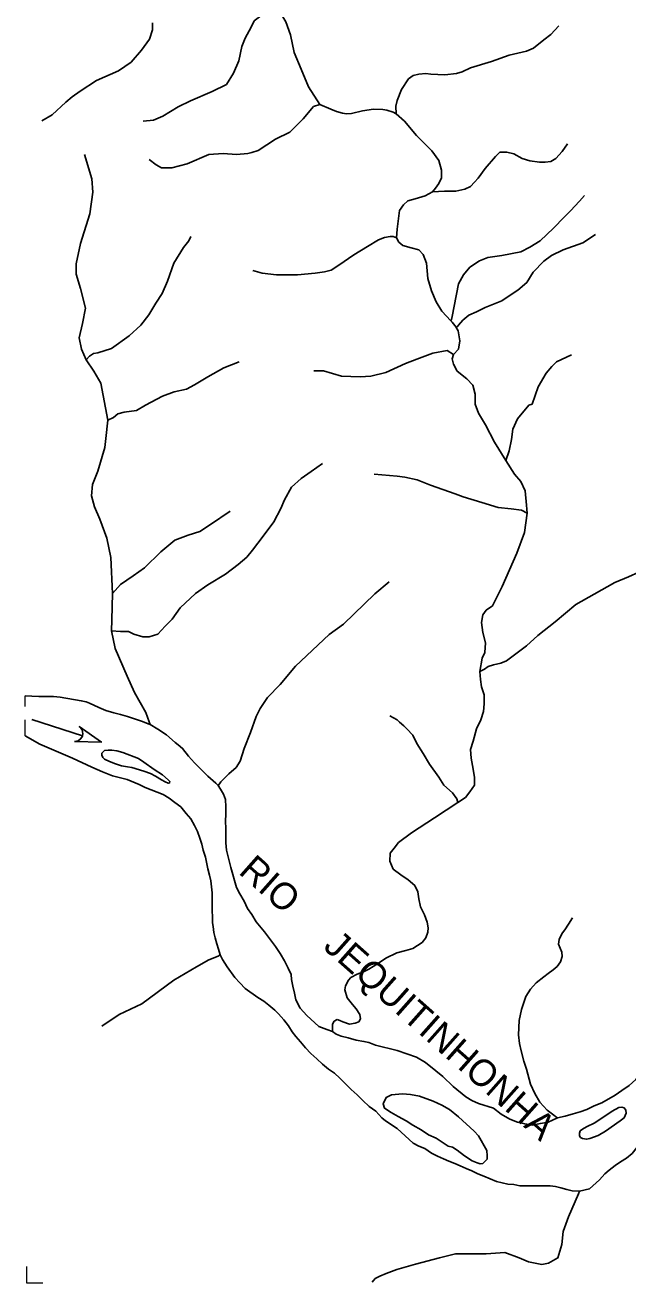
# Model space of a CAD drawing. Extents: x 436.3 to 500.4, y 8231 to 8286.4.
# Drawn here: x 446.49 to 451, y 8230.98 to 8240.38 of the extents above; entities that cross this region are included whole.
import ezdxf
from ezdxf.enums import TextEntityAlignment as Align

# ---------------------------------------------------------------- set-up
doc = ezdxf.new("R2010")
doc.units = 0
doc.header["$LTSCALE"] = 0.08
doc.linetypes.add('LONG_DASHED', pattern=[7.5, 6, -1.5])
doc.linetypes.add('SHORT_DASHED', pattern=[2.7, 1.5, -1.2])
for name, color, linetype, lineweight in [('10', 7, 'Continuous', 25), ('2', 7, 'Continuous', 25), ('62', 7, 'SHORT_DASHED', 13), ('63', 7, 'Continuous', 13), ('7', 7, 'Continuous', 25), ('9', 7, 'LONG_DASHED', 25)]:
    doc.layers.add(name, color=color, linetype=linetype, lineweight=lineweight)
doc.layers.add('61', color=7, linetype='Continuous')

msp = doc.modelspace()

# ---------------------------------------------------------------- linework, layer by layer
at = {"layer": '10'}
msp.add_line((446.5406, 8235.1881), (446.919, 8235.0658), dxfattribs=at)
msp.add_lwpolyline([(446.859, 8235.0241), (446.8761, 8235.0264), (446.8873, 8235.0299), (446.9031, 8235.0408), (446.9166, 8235.0591), (446.919, 8235.0658), (446.9219, 8235.0823), (446.9204, 8235.0973), (446.9164, 8235.1116), (446.908, 8235.1238), (446.8951, 8235.1357), (447.0619, 8235.0197)], close=True, dxfattribs=at)
at = {"layer": '2'}
for points in [[(447.4257, 8235.1524), (447.4106, 8235.1558), (447.3801, 8235.1688), (447.3615, 8235.1755), (447.2577, 8235.2116), (447.2035, 8235.2251), (447.1539, 8235.2387), (447.0952, 8235.2567), (447.0411, 8235.2793), (446.9734, 8235.3108), (446.9463, 8235.3198), (446.9102, 8235.3289), (446.7522, 8235.3561), (446.7026, 8235.3607), (446.5943, 8235.3608), (446.5402, 8235.363), (446.4909, 8235.3646)], [(447.9336, 8234.6948), (447.9163, 8234.712), (447.8577, 8234.766), (447.7584, 8234.8649), (447.7133, 8234.9144), (447.6682, 8234.9729), (447.6367, 8234.9999), (447.6141, 8235.0179), (447.5484, 8235.0732), (447.4833, 8235.1169), (447.4257, 8235.1524)], [(446.4916, 8235.0661), (446.6012, 8235.0056), (446.8464, 8234.8998), (446.9905, 8234.8321), (447.0699, 8234.799), (447.1445, 8234.767), (447.2529, 8234.7399), (447.3431, 8234.7038), (447.3882, 8234.6813), (447.5236, 8234.6272), (447.5687, 8234.6001), (447.6094, 8234.5686), (447.6545, 8234.5371), (447.6951, 8234.4876), (447.7312, 8234.4472), (447.7582, 8234.3977), (447.7808, 8234.3527), (447.7988, 8234.3033), (447.8123, 8234.2583), (447.8213, 8234.2134), (447.8393, 8234.1595), (447.8573, 8234.0741), (447.8708, 8234.0246), (447.8799, 8233.9842), (447.8888, 8233.8943), (447.8887, 8233.7595), (447.8932, 8233.7146), (447.8932, 8233.6697), (447.8977, 8233.6427), (447.9022, 8233.5978), (447.9112, 8233.5573), (447.9247, 8233.5124), (447.9382, 8233.4719), (447.9495, 8233.4305)], [(448.5157, 8233.0936), (448.5067, 8233.1431), (448.4932, 8233.197), (448.4842, 8233.2464), (448.4797, 8233.2824), (448.4572, 8233.3318), (448.4302, 8233.3858), (448.3986, 8233.4397), (448.3625, 8233.4937), (448.2814, 8233.6017), (448.2182, 8233.6781), (448.1866, 8233.7321), (448.1551, 8233.7771), (448.128, 8233.831), (448.0965, 8233.885), (448.0727, 8233.9344), (448.0297, 8234.0827), (447.9973, 8234.2131), (447.9928, 8234.2671), (447.9929, 8234.3749), (447.9884, 8234.4288), (447.9929, 8234.4827), (447.993, 8234.5366), (447.9885, 8234.5906), (447.975, 8234.631), (447.9509, 8234.6684), (447.9336, 8234.6948)], [(447.9495, 8233.4305), (447.9678, 8233.3964), (448.0013, 8233.3415), (448.06, 8233.2606), (448.0961, 8233.2201), (448.1367, 8233.1796), (448.2314, 8233.112), (448.2765, 8233.085), (448.3126, 8233.0535), (448.3577, 8233.0175), (448.3848, 8232.9905), (448.4254, 8232.9455), (448.4614, 8232.9005), (448.4885, 8232.8556), (448.5155, 8232.8196), (448.5516, 8232.7791), (448.5876, 8232.7341), (448.6282, 8232.6936), (448.6733, 8232.6532), (448.7138, 8232.6127), (448.7589, 8232.5767), (448.804, 8232.5452), (448.8445, 8232.5092), (448.9301, 8232.4238), (448.9752, 8232.3833), (449.0157, 8232.3428), (449.0653, 8232.2979), (449.1148, 8232.2619), (449.1599, 8232.2124), (449.1869, 8232.19), (449.2725, 8232.1315), (449.3941, 8232.0236), (449.4346, 8232.0011), (449.4797, 8231.9831), (449.5292, 8231.9471), (449.5743, 8231.9246), (449.6193, 8231.9066), (449.6599, 8231.8886), (449.7049, 8231.8706), (449.7455, 8231.8526), (449.7905, 8231.8346), (449.8311, 8231.8166), (449.8761, 8231.7941), (449.9212, 8231.7761), (450.0158, 8231.7356), (450.1014, 8231.7176), (450.1465, 8231.713), (450.1915, 8231.704), (450.4169, 8231.7038), (450.4575, 8231.6993), (450.498, 8231.6903), (450.5431, 8231.6768), (450.5836, 8231.6677), (450.6384, 8231.6632)], [(448.7889, 8232.8575), (448.7479, 8232.8729), (448.687, 8232.8957), (448.5969, 8232.9767), (448.5473, 8233.0307), (448.5157, 8233.0936)], [(450.4733, 8232.2117), (450.4359, 8232.1958), (450.404, 8232.1799), (450.3454, 8232.171), (450.2868, 8232.1576), (450.2282, 8232.1666), (450.1742, 8232.1801), (450.1156, 8232.2026), (450.0525, 8232.2386), (449.994, 8232.2836), (449.8813, 8232.3196), (449.8318, 8232.3421), (449.7867, 8232.3691), (449.6922, 8232.4455), (449.6156, 8232.5219), (449.5616, 8232.5624), (449.485, 8232.6254), (449.4174, 8232.6659), (449.2732, 8232.7154), (449.1109, 8232.756), (449.0613, 8232.774), (449.0252, 8232.783), (448.9666, 8232.7921), (448.908, 8232.8101), (448.8539, 8232.8236), (448.8178, 8232.8372), (448.7889, 8232.8575)], [(451.5338, 8232.7256), (451.504, 8232.7208), (451.4903, 8232.7185), (451.4588, 8232.7185), (451.3957, 8232.7095), (451.3371, 8232.6961), (451.3056, 8232.6871), (451.2155, 8232.6422), (451.1614, 8232.6018), (451.1028, 8232.5524), (451.0577, 8232.4985), (451.0081, 8232.4536), (450.954, 8232.4177), (450.9044, 8232.3818), (450.8052, 8232.3234), (450.7466, 8232.301), (450.6925, 8232.2741), (450.6429, 8232.2561), (450.5888, 8232.2427), (450.5302, 8232.2248), (450.4733, 8232.2117)], [(450.9895, 8231.91), (451.0301, 8231.9459), (451.1068, 8232.0402), (451.1925, 8232.1794), (451.2151, 8232.2198), (451.2422, 8232.2603), (451.3053, 8232.3411)], [(450.6384, 8231.6632), (450.7113, 8231.6824), (450.7865, 8231.7484), (450.8271, 8231.7933), (450.8587, 8231.8202), (450.9038, 8231.8561), (450.9444, 8231.8831), (450.9895, 8231.91)]]:
    msp.add_lwpolyline(points, dxfattribs=at)
for points in [[(447.1402, 8234.9602), (447.112, 8234.9602), (447.0848, 8234.9583), (447.065, 8234.9362), (447.065, 8234.9215), (447.0724, 8234.9043), (447.0847, 8234.892), (447.122, 8234.8749), (447.1672, 8234.8568), (447.2123, 8234.8433), (447.2574, 8234.8342), (447.289, 8234.8297), (447.3793, 8234.8026), (447.4289, 8234.7845), (447.465, 8234.7665), (447.5117, 8234.7392), (447.5388, 8234.722), (447.5611, 8234.7122), (447.5709, 8234.7145), (447.5734, 8234.7244), (447.5611, 8234.7391), (447.5192, 8234.7754), (447.456, 8234.8159), (447.3793, 8234.87), (447.3387, 8234.897), (447.2214, 8234.9421), (447.1763, 8234.9556)], [(449.2322, 8232.383), (449.1916, 8232.3651), (449.169, 8232.3157), (449.178, 8232.2843), (449.2276, 8232.2528), (449.2816, 8232.2213), (449.3402, 8232.1898), (449.3898, 8232.1583), (449.4528, 8232.1223), (449.5069, 8232.0863), (449.5655, 8232.0593), (449.6555, 8232.0009), (449.6871, 8231.9919), (449.7231, 8231.9694), (449.7772, 8231.9289), (449.8346, 8231.8914), (449.871, 8231.8749), (449.8942, 8231.8683), (449.914, 8231.8716), (449.9471, 8231.9045), (449.9472, 8231.9276), (449.9439, 8231.9671), (449.881, 8232.077), (449.8495, 8232.113), (449.7325, 8232.2209), (449.6649, 8232.2748), (449.6064, 8232.3063), (449.5433, 8232.3378), (449.4396, 8232.3738), (449.372, 8232.3874), (449.3134, 8232.3919)], [(450.6592, 8232.1279), (450.6427, 8232.1148), (450.636, 8232.0983), (450.636, 8232.0786), (450.6459, 8232.0654), (450.6591, 8232.0588), (450.6889, 8232.0522), (450.7148, 8232.0584), (450.7779, 8232.0808), (450.832, 8232.1123), (450.9404, 8232.1904), (450.9702, 8232.2134), (450.9868, 8232.2463), (450.9835, 8232.2694), (450.9703, 8232.2859), (450.9538, 8232.2925), (450.9306, 8232.2892), (450.8809, 8232.2629), (450.7519, 8232.174), (450.689, 8232.1444)]]:
    msp.add_lwpolyline(points, close=True, dxfattribs=at)
at = {"layer": '62'}
msp.add_line((446.4916, 8235.0661), (446.4909, 8235.3646), dxfattribs=at)
at = {"layer": '63'}
msp.add_lwpolyline([(446.5014, 8231.1023), (446.5014, 8230.9791), (446.6228, 8230.9791)], dxfattribs=at)
at = {"layer": '7'}
msp.add_line((450.6384, 8231.6632), (450.6305, 8231.6443), dxfattribs=at)
msp.add_lwpolyline([(450.6305, 8231.6443), (450.5556, 8231.4724), (450.5157, 8231.3636), (450.5056, 8231.2646), (450.4756, 8231.1658), (450.4059, 8231.1262), (450.3562, 8231.1164), (450.2567, 8231.1363), (450.1872, 8231.1661), (450.0779, 8231.2058), (449.9386, 8231.196), (449.7795, 8231.1962), (449.7099, 8231.1963), (449.5904, 8231.1668), (449.4113, 8231.1175), (449.2719, 8231.0783), (449.1922, 8231.0487), (449.1432, 8231.0287), (449.1101, 8231.011), (449.087, 8230.9851)], dxfattribs=at)
at = {"layer": '9'}
for p, q in [((448.694, 8239.7856), (448.7781, 8239.7493)), ((448.7902, 8232.8734), (448.7889, 8232.8575))]:
    msp.add_line(p, q, dxfattribs=at)
for points in [[(447.3741, 8239.6601), (447.451, 8239.6677), (447.5202, 8239.6982), (447.6356, 8239.7669), (447.7277, 8239.8128), (447.8891, 8239.8815), (447.9969, 8239.935), (448.0506, 8240.0192), (448.0892, 8240.111), (448.1123, 8240.2183), (448.1354, 8240.2794), (448.1816, 8240.3636), (448.2047, 8240.4096), (448.2739, 8240.4631), (448.3046, 8240.4937), (448.3348, 8240.5227)], [(448.3348, 8240.5227), (448.3357, 8240.5218), (448.4029, 8240.4643), (448.4413, 8240.4021), (448.4749, 8240.3064), (448.5036, 8240.1723), (448.5563, 8240.0479), (448.6096, 8239.9156), (448.694, 8239.7856)], [(446.6161, 8239.6634), (446.6928, 8239.7072), (446.7957, 8239.8023), (446.843, 8239.8411), (446.9014, 8239.8849), (447.0249, 8239.9647), (447.1899, 8240.0354), (447.2849, 8240.0999), (447.3618, 8240.1917), (447.4206, 8240.2724), (447.4436, 8240.3426), (447.4437, 8240.3961)], [(450.4815, 8240.3715), (450.424, 8240.309), (450.3716, 8240.2674), (450.2932, 8240.2048), (450.2409, 8240.184), (450.1102, 8240.1528), (449.9795, 8240.1061), (449.8227, 8240.0592), (449.7599, 8240.0279), (449.7181, 8240.0176), (449.6292, 8240.0072), (449.5247, 8240.0124), (449.4881, 8240.0176), (449.4358, 8240.0124), (449.394, 8240.0021), (449.3573, 8239.976), (449.305, 8239.8979), (449.2735, 8239.8146), (449.2631, 8239.7729), (449.2651, 8239.7155)], [(447.418, 8239.3732), (447.4718, 8239.3349), (447.5102, 8239.312), (447.5871, 8239.3119), (447.7024, 8239.3423), (447.8638, 8239.411), (447.9714, 8239.4186), (448.0713, 8239.4109), (448.1558, 8239.4185), (448.1866, 8239.4261), (448.2327, 8239.4413), (448.3634, 8239.5255), (448.471, 8239.579), (448.571, 8239.6784), (448.6479, 8239.7702), (448.694, 8239.7856)], [(448.7781, 8239.7493), (448.8203, 8239.7324), (448.8639, 8239.7207), (448.8943, 8239.7155), (448.9324, 8239.7175), (449.0147, 8239.7376), (449.0956, 8239.7493), (449.1655, 8239.748), (449.1967, 8239.7434), (449.243, 8239.7285), (449.2651, 8239.7155)], [(449.2651, 8239.7155), (449.3295, 8239.66), (449.4169, 8239.5523), (449.5321, 8239.4374), (449.5849, 8239.3656), (449.604, 8239.2939), (449.604, 8239.2364), (449.5847, 8239.1934), (449.5606, 8239.1599), (449.5367, 8239.1312)], [(450.5475, 8239.4899), (450.5066, 8239.4324), (450.4594, 8239.3803), (450.4229, 8239.3595), (450.3811, 8239.3543), (450.3393, 8239.3543), (450.2661, 8239.3649), (450.2087, 8239.3805), (450.146, 8239.417), (450.0937, 8239.4274), (450.0415, 8239.4274), (450.0101, 8239.3961), (449.9315, 8239.3076), (449.8793, 8239.2348), (449.8531, 8239.2036), (449.8217, 8239.1724), (449.7799, 8239.1516), (449.7119, 8239.136), (449.6283, 8239.136), (449.5367, 8239.1312)], [(446.9357, 8239.4119), (446.9894, 8239.2282), (446.9971, 8239.1288), (446.974, 8238.9682), (446.9047, 8238.7465), (446.8738, 8238.5935), (446.8738, 8238.517), (446.9045, 8238.4099), (446.9424, 8238.2617), (446.9193, 8238.147), (446.8961, 8238.04), (446.9114, 8237.9559), (446.9485, 8237.8757)], [(449.5367, 8239.1312), (449.4838, 8239.1026), (449.4069, 8239.0786), (449.3541, 8239.0644), (449.3204, 8239.0357), (449.2916, 8238.9927), (449.2723, 8238.854), (449.2674, 8238.7895)], [(450.6735, 8239.1043), (450.6368, 8239.0627), (450.5688, 8238.9898), (450.5217, 8238.9431), (450.4433, 8238.8598), (450.3439, 8238.7662), (450.2655, 8238.7193), (450.1975, 8238.683), (450.0564, 8238.657), (449.9519, 8238.6415), (449.8892, 8238.6154), (449.816, 8238.5686), (449.7689, 8238.5114), (449.7322, 8238.4438), (449.7008, 8238.2773), (449.6859, 8238.1993), (449.6795, 8238.1775), (449.6761, 8238.1674)], [(447.6021, 8238.5979), (447.6756, 8238.7167), (447.7163, 8238.7666), (447.7302, 8238.7976)], [(448.1941, 8238.5434), (448.2634, 8238.5242), (448.371, 8238.5127), (448.5288, 8238.5126), (448.6596, 8238.524), (448.7289, 8238.5354), (448.7789, 8238.5469), (448.8366, 8238.5851), (448.9482, 8238.6617), (449.0524, 8238.7229), (449.1332, 8238.7727), (449.1794, 8238.7917), (449.2217, 8238.7994), (449.2448, 8238.7994), (449.2674, 8238.7895)], [(449.2674, 8238.7895), (449.2866, 8238.7559), (449.3155, 8238.732), (449.3779, 8238.7129), (449.4355, 8238.6985), (449.4691, 8238.665), (449.4931, 8238.5981), (449.5026, 8238.4834), (449.5313, 8238.3925), (449.5649, 8238.3111), (449.608, 8238.2394), (449.6761, 8238.1674)], [(450.7567, 8238.8128), (450.6626, 8238.7504), (450.5163, 8238.6984), (450.4275, 8238.6566), (450.37, 8238.6151), (450.2915, 8238.5319), (450.2444, 8238.4539), (450.1764, 8238.3966), (450.1032, 8238.3499), (450.0562, 8238.3186), (449.9308, 8238.2667), (449.868, 8238.2354), (449.8105, 8238.2095), (449.7635, 8238.1731), (449.7324, 8238.135), (449.7268, 8238.1282), (449.716, 8238.1179)], [(446.9485, 8237.8757), (446.972, 8237.9034), (447.0026, 8237.9229), (447.0359, 8237.9296), (447.1358, 8237.9625), (447.269, 8238.0551), (447.3557, 8238.1345), (447.4155, 8238.2139), (447.4688, 8238.2999), (447.5155, 8238.3728), (447.5555, 8238.4654), (447.6021, 8238.5979)], [(449.6761, 8238.1674), (449.6848, 8238.1582), (449.7151, 8238.1196), (449.716, 8238.1179)], [(449.716, 8238.1179), (449.7302, 8238.0922), (449.7423, 8238.0176), (449.7327, 8237.9554), (449.6943, 8237.9171)], [(448.6497, 8237.7955), (448.7229, 8237.7955), (448.856, 8237.7557), (448.9958, 8237.749), (449.0755, 8237.7555), (449.1887, 8237.7819), (449.3351, 8237.8482), (449.4216, 8237.8812), (449.5414, 8237.9276), (449.6479, 8237.9474), (449.6943, 8237.9171)], [(446.9485, 8237.8757), (447.004, 8237.7929), (447.0574, 8237.7034), (447.1106, 8237.427)], [(448.0907, 8237.8621), (447.9776, 8237.8159), (447.8577, 8237.7498), (447.7578, 8237.6902), (447.6979, 8237.6572), (447.6047, 8237.6374), (447.5182, 8237.6044), (447.3916, 8237.5382), (447.325, 8237.4986), (447.2319, 8237.4855), (447.1853, 8237.4723), (447.152, 8237.4459), (447.1106, 8237.427)], [(449.6943, 8237.9171), (449.6846, 8237.8837), (449.6942, 8237.8454), (449.723, 8237.7929), (449.7949, 8237.7355), (449.8382, 8237.6876), (449.8573, 8237.6207), (449.8572, 8237.5442), (449.8812, 8237.4773), (449.9339, 8237.3913), (450.0011, 8237.2622), (450.0874, 8237.1236)], [(450.5767, 8237.9135), (450.465, 8237.8622), (450.4306, 8237.828), (450.3876, 8237.7767), (450.3274, 8237.6741), (450.2842, 8237.5461), (450.2585, 8237.5376), (450.1725, 8237.435), (450.1381, 8237.358), (450.1295, 8237.2811), (450.1122, 8237.1955), (450.0874, 8237.1236)], [(447.1106, 8237.427), (447.0952, 8237.2894), (447.0875, 8237.2206), (447.0336, 8237.0448), (446.9952, 8236.9455), (446.9874, 8236.8614), (447.0104, 8236.7773), (447.0488, 8236.6855), (447.1021, 8236.545), (447.1327, 8236.3997), (447.145, 8236.1311)], [(448.7162, 8237.1027), (448.6297, 8237.0432), (448.5565, 8236.9902), (448.4832, 8236.924), (448.43, 8236.8313), (448.4034, 8236.7651), (448.35, 8236.6658), (448.2702, 8236.56), (448.1903, 8236.454), (448.1502, 8236.4011), (448.0837, 8236.3482), (447.9905, 8236.2755), (447.8573, 8236.1961), (447.7641, 8236.1299), (447.6508, 8236.0241), (447.5909, 8235.9381), (447.5376, 8235.8852), (447.4843, 8235.8256), (447.4177, 8235.8058), (447.3711, 8235.8059), (447.3046, 8235.8259), (447.2646, 8235.8458), (447.2047, 8235.8458), (447.1381, 8235.8526)], [(450.0874, 8237.1236), (450.1505, 8237.0213), (450.1984, 8236.9686), (450.2319, 8236.8969), (450.2415, 8236.7918), (450.2466, 8236.7306)], [(449.1008, 8237.0223), (449.2733, 8237.007), (449.3318, 8237.0008), (449.4243, 8236.9793), (449.5229, 8236.9394), (449.7076, 8236.8749), (449.7661, 8236.8534), (449.9079, 8236.8105), (450.0279, 8236.7736), (450.1265, 8236.7644), (450.2035, 8236.7521), (450.2466, 8236.7306)], [(448.0241, 8236.746), (447.8776, 8236.6469), (447.7977, 8236.5939), (447.7111, 8236.5676), (447.6113, 8236.5279), (447.5047, 8236.4419), (447.3848, 8236.3229), (447.2982, 8236.2634), (447.205, 8236.1973), (447.145, 8236.1311)], [(450.2466, 8236.7306), (450.2269, 8236.5862), (450.169, 8236.4312), (450.0585, 8236.1827), (449.9864, 8236.0393), (449.9384, 8236.0058), (449.9144, 8235.9723), (449.9048, 8235.915), (449.9143, 8235.8385), (449.9336, 8235.762), (449.9287, 8235.6903), (449.9095, 8235.6473), (449.8928, 8235.5472)], [(451.0819, 8236.2889), (451.0047, 8236.2547), (450.9016, 8236.2119), (450.747, 8236.1265), (450.6096, 8236.0495), (450.4551, 8235.919), (450.3263, 8235.8165), (450.2405, 8235.7395), (450.0919, 8235.6271), (450.0482, 8235.6103), (449.9943, 8235.5977), (449.953, 8235.585), (449.9277, 8235.5662), (449.8928, 8235.5472)], [(449.2138, 8236.2182), (449.1059, 8236.1288), (448.8722, 8235.9023), (448.7643, 8235.8248), (448.5125, 8235.5864), (448.3986, 8235.4493), (448.3027, 8235.3541), (448.2487, 8235.2706), (448.2187, 8235.211), (448.1767, 8235.0918), (448.1287, 8234.9725), (448.0987, 8234.8772), (448.0687, 8234.8295), (448.0147, 8234.7818), (447.9547, 8234.7223), (447.9448, 8234.7075), (447.9336, 8234.6948)], [(447.145, 8236.1311), (447.1402, 8235.9334), (447.1381, 8235.8526)], [(447.1381, 8235.8526), (447.1646, 8235.7201), (447.2553, 8235.5127), (447.309, 8235.3904), (447.3936, 8235.2409), (447.4193, 8235.172), (447.4257, 8235.1524)], [(449.8928, 8235.5472), (449.8959, 8235.4872), (449.9054, 8235.4334), (449.924, 8235.3721), (449.924, 8235.3052), (449.9192, 8235.2479), (449.8999, 8235.1856), (449.8664, 8235.1187), (449.8423, 8235.028), (449.8231, 8234.9657), (449.8279, 8234.8988), (449.8423, 8234.8175), (449.8519, 8234.7554), (449.8519, 8234.698), (449.818, 8234.6489), (449.7844, 8234.6059), (449.7269, 8234.5694)], [(449.2187, 8235.2169), (449.2729, 8235.1869), (449.2909, 8235.1689), (449.324, 8235.1419), (449.345, 8235.118), (449.3902, 8235.073), (449.4202, 8235.0101), (449.4684, 8234.9351), (449.5164, 8234.8542), (449.5856, 8234.7583), (449.6217, 8234.6983), (449.6879, 8234.6414), (449.7209, 8234.5964), (449.7269, 8234.5694)], [(449.7269, 8234.5694), (449.5539, 8234.453), (449.3802, 8234.3419), (449.2842, 8234.2702), (449.2505, 8234.2273), (449.2217, 8234.1891), (449.2184, 8234.1297), (449.2448, 8234.071), (449.3007, 8234.027), (449.3566, 8233.9918), (449.4066, 8233.9479), (449.4272, 8233.901), (449.436, 8233.8483), (449.4477, 8233.7896), (449.4772, 8233.7281), (449.4978, 8233.6753), (449.5066, 8233.6314), (449.5036, 8233.5991), (449.4889, 8233.5581), (449.4595, 8233.523), (449.3912, 8233.4776), (449.3382, 8233.4629), (449.2706, 8233.4454), (449.1882, 8233.4045), (449.1263, 8233.3635), (449.0616, 8233.3226), (449.0262, 8233.305), (448.9733, 8233.2846), (448.9261, 8233.2612), (448.9085, 8233.2407), (448.8878, 8233.1997), (448.8819, 8233.1676), (448.9004, 8233.1093), (448.9386, 8233.0603), (448.9661, 8233.0275), (448.9934, 8232.9839), (448.9988, 8232.9512), (448.9879, 8232.9294), (448.9605, 8232.9186), (448.9167, 8232.9131), (448.8674, 8232.9296), (448.8454, 8232.9405), (448.8236, 8232.9459), (448.8016, 8232.935), (448.7907, 8232.9133), (448.7902, 8232.8734)], [(450.585, 8233.7078), (450.5561, 8233.6597), (450.5268, 8233.6176), (450.5093, 8233.5935), (450.5036, 8233.5815), (450.4862, 8233.5455), (450.4809, 8233.5097), (450.5058, 8233.4506), (450.5081, 8233.4184), (450.495, 8233.3768), (450.4713, 8233.3442), (450.4406, 8233.3172), (450.4018, 8233.2902), (450.3699, 8233.2655), (450.3126, 8233.221), (450.2716, 8233.1728), (450.2367, 8233.1186), (450.2024, 8233.0228), (450.1859, 8232.9392), (450.1817, 8232.8319), (450.1888, 8232.7667), (450.2015, 8232.7134), (450.2208, 8232.6363), (450.2397, 8232.5771), (450.2714, 8232.4647), (450.3025, 8232.3938), (450.3395, 8232.3289), (450.3942, 8232.2704), (450.4444, 8232.233), (450.4565, 8232.2227), (450.4733, 8232.2117)], [(447.0635, 8232.8966), (447.1931, 8232.9852), (447.3627, 8233.064), (447.6021, 8233.2416), (447.7715, 8233.3402), (447.8658, 8233.3921), (447.9354, 8233.4206), (447.9495, 8233.4305)]]:
    msp.add_lwpolyline(points, dxfattribs=at)

# ---------------------------------------------------------------- texts
at = {"layer": '61'}
msp.add_text('RIO     JEQUITINHONHA', height=0.2, rotation=318.403, dxfattribs=at).set_placement((449.213, 8233.0364), align=Align.CENTER)

doc.saveas('drawing.dxf')
